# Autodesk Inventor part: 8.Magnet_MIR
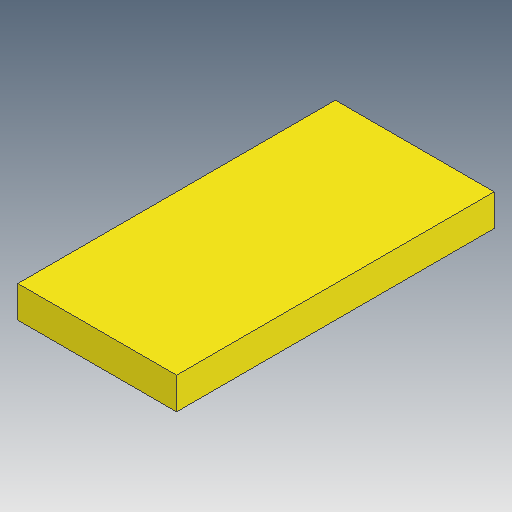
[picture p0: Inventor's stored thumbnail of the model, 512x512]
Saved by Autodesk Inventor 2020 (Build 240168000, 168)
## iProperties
Created: 2022-02
Part Number: 8.Magnet_MIR
Material: Steel
Document SubType Name: Modeling
Designer: marti
Mass: 3.14 g
Surface Area: 5.2 cm^2
Volume: 0.4 cm^3
Density: 7.85 g/cm^3
Appearance: Plate
Author: marti
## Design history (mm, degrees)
derived "8.Magnet.ipt"
  sketch "Sketch1"
    geometry: L1 (-5, 10)-(5, 10) reference; L2 (5, 10)-(5, -10) reference; L3 (5, -10)-(-5, -10) reference; L4 (-5, -10)-(-5, 10) reference; L5 (-5, 10)-(5, -10) reference; L6 (5, 10)-(-5, -10) reference; 1 further point
    dimensions: "d0" = 10 dimension on point (0, 0) L1.start L2.end L1.end L3.end L1 L2 L3 L4 L5 L6
feature "Solid1::8.Magnet.ipt" dims "d0" = 10
tag "TaggingFeature1"
body "Solid1"
